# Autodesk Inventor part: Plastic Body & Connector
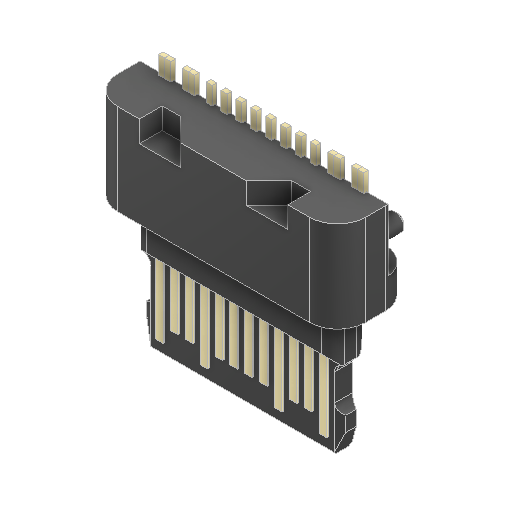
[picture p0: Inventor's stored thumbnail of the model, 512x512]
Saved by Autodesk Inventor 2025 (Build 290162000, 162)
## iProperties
Created: 2025-05
Part Number: Plastic Body & Connector
Material: Acier
Document SubType Name: Modeling
Designer: R5800u
Density: 7.85 g/cm^3
Appearance: Default
Author: R5800u
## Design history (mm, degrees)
feature "Corps1"
node "Solido1"
